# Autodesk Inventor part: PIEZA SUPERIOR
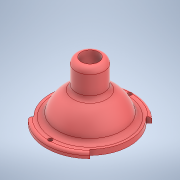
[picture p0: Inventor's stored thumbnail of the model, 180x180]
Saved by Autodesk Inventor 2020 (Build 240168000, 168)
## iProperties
Created: 2022-09
Part Number: PIEZA SUPERIOR
Material: Tuberías de PVC
Document SubType Name: Modeling
Designer: SEBAS
Density: 1.4 g/cm^3
Appearance: Suave - Rojo
Author: SEBAS
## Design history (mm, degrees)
sketch "Boceto1"
  geometry: L1 (0, 0)-(0, 14.523); L2 (-34.5, 0)-(-34.5, 4); L3 (-34.5, 4)-(-24.5, 4); L4 (-10.48, 22.504)-(-10.48, 42.504); L5 (-10.48, 42.504)-(-6.48, 42.504); L6 (-6.48, 42.504)-(-6.48, 0); L7 (-34.5, 0)-(-6.48, 0); A1 r 24.824 centre (0, 0) between (-10.48, 22.504) and (-24.5, 4)
  constraints: 14 end point, 4 perpendicular, 3 vertical, 2 point on circle, 1 centre point, 1 coincident, 1 horizontal, 1 horizontal alignment
  dimensions: "d0" = 34.5 distance of L1.start L2.start; "d1" = 4 distance of L2.start L2.end; "d2" = 20.96 diameter of L4 L1; "d3" = 10 distance of L2.end L3.end; "d4" = 20 vertical distance of L4.start L5.end
revolve "Revolución1" sketch "Boceto1" stored, may be unused: angle "d5" = 90 deg
sketch "Boceto2"
  geometry: L1 (34.5, 0)-(0, 0); L2 (0, 0)-(24.395, -24.395); L3 (0, 0)-(-24.395, 24.395); L4 (0, 0)-(-24.395, -24.395); L5 (0, 0)-(24.395, 24.395); L6 (0, 0)-(-34.5, 0); L7 (0, 34.5)-(0, 24.5); L8 (0, -34.5)-(0, -24.5); C1 r 34.5 at (0, 0) reference; C2 r 1.5 at (0, 29.5); C3 r 1.5 at (0, -29.5); C4 r 32.5 at (0, 0); A1 r 24.5 centre (0, 0) between (0, 24.5) and (0, -24.5) reference; 14 further points
  constraints: 16 end point, 3 centre point, 3 coincident, 2 horizontal, 2 midpoint, 2 point on circle, 2 point on line, 1 equal radius, 1 vertical, 1 vertical alignment, 14 other
  dimensions: "d7" = 45 deg angle of L1 L2; "d8" = 45 deg angle of L6 L4; "d9" = 45 deg angle of L5 L1; "d10" = 45 deg angle of L6 L3; "d15" = 3 diameter of C2; "d18" = 2 radial gap between concentric circles of C1 C4
extrude "Extrusión1" cut sketch "Boceto2" distance "d11" = 10; taper "d12" = 0 deg
extrude "Extrusión2" cut sketch "Boceto2" distance "d16" = 10; taper "d17" = 0 deg
extrude "Extrusión3" cut sketch "Boceto2" distance "d19" = 10; taper "d20" = 0 deg
fillet "Empalme3" dims "d21" = 2
fillet "Empalme4" dims "d22" = 4
node "Sólido1"
